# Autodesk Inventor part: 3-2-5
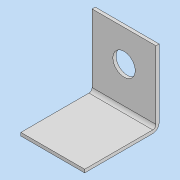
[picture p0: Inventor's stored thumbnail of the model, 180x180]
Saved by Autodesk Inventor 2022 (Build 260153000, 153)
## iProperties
Created: 2021-07
Part Number: 3-2-5
Material: 一般
Document SubType Name: Modeling
Designer: DesignLab
Density: 1 g/cm^3
Appearance: 既定
Author: DesignLab
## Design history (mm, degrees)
sketch "スケッチ1"
  geometry: L1 (0, 0)-(70, 0); L2 (70, 0)-(70, 70); L3 (70, 70)-(0, 70); L4 (0, 70)-(0, 0)
  constraints: 8 end point, 2 parallel, 1 horizontal, 1 perpendicular
  dimensions: "d0" = 70 distance of L3.end L2.end; "d1" = 70 distance of L2.end L1.end
extrude "押し出し1" new body sketch "スケッチ1" stored distance "d2" = 60; taper "d3" = 0 deg
fillet "フィレット1" dims "d4" = 6
feature "シェル1" dims "d5" = 3
sketch "スケッチ2"
  geometry: L1 (0, -6)-(60, -6) reference; 3 further points
  constraints: 1 midpoint, 1 vertical alignment
  dimensions: "d6" = 40 distance from line of point (30, 34) L1
hole "穴1" sketch "スケッチ2" at (30, 34) diameter "d7" = 21; stored, may be unused: countersink angle "d11" = 90 deg, drill point angle "d13" = 118 deg; dims "d8" = 6, "d9" = 4, "d10" = 2, "d12" = 8
node "ソリッド1"
